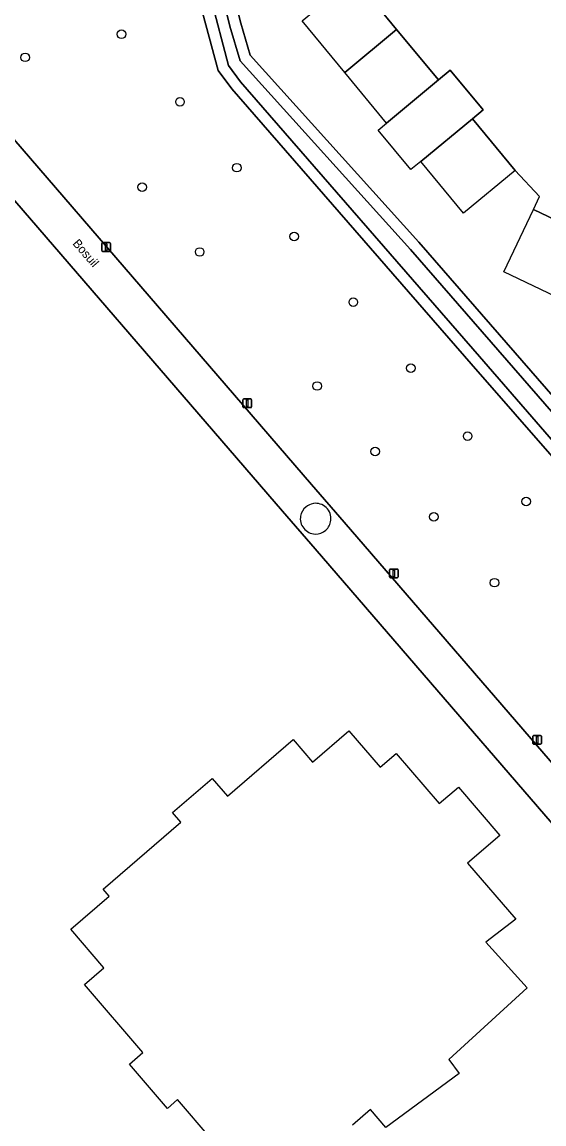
# Model space of a CAD drawing. Extents: x 156661 to 157576, y 383570 to 384425.
# Drawn here: x 156830 to 156889.4, y 383755 to 383880.2 of the extents above; entities that cross this region are included whole.
import ezdxf

# ---------------------------------------------------------------- set-up
doc = ezdxf.new("R2010")
doc.units = 0
for name, color, linetype in [('IMGEO_Boom', 7, 'Continuous'), ('IMGEO_Groenvoorziening', 7, 'Continuous'), ('IMGEO_Lichtmast', 7, 'Continuous'), ('IMGEO_Oever', 7, 'Continuous'), ('IMGEO_Openbare_ruimte_label', 7, 'Continuous'), ('IMGEO_Pand_vergunning_verleend', 7, 'Continuous'), ('IMGEO_Rijbaan_lokaal_gesloten', 7, 'Continuous'), ('IMGEO_Rijbaan_lokaal_open', 7, 'Continuous'), ('IMGEO_Waterloop', 7, 'Continuous')]:
    doc.layers.add(name, color=color, linetype=linetype)

msp = doc.modelspace()

# ---------------------------------------------------------------- linework, layer by layer
at = {"layer": 'IMGEO_Boom'}
for centre in [(156841.29, 383878.84), (156830.33, 383876.22), (156847.96, 383871.17), (156854.42, 383863.68), (156843.66, 383861.47), (156860.94, 383855.86), (156850.2, 383854.1), (156867.68, 383848.4), (156874.22, 383840.9), (156863.58, 383838.87), (156880.69, 383833.18), (156870.17, 383831.43), (156887.36, 383825.74), (156876.85, 383823.99), (156883.74, 383816.52)]:
    msp.add_circle(centre, 0.489, dxfattribs=at)
at = {"layer": 'IMGEO_Groenvoorziening'}
for points in [[(156851.52, 383893.46), (156854.87, 383880.1), (156855.95, 383876.48), (156875.13, 383855.23), (156891.46, 383836.51), (156911.62, 383812.79), (156912.8, 383811.32), (156913.72, 383811.62), (156932.37, 383827.97), (156950.38, 383842.94), (156962.3, 383852.37), (156962.64, 383852.87), (156967.11, 383858.58), (156983.42, 383879.38)], [(156930.61, 383784.8), (156881.09, 383841.39), (156853.84, 383872.65), (156852.3, 383874.71), (156848.11, 383890.33), (156847.87, 383891.87)], [(156820.25, 383877.09), (156862.92, 383827.69), (156866.64, 383823.38), (156904.91, 383779.13), (156906.37, 383777.46), (156907.59, 383778.51), (156909.46, 383776.35)], [(156863.33, 383820.38), (156859.63, 383824.66), (156822.23, 383867.92), (156821.46, 383867.3), (156814.7, 383875.12)], [(156903.48, 383771.4), (156901.63, 383773.6), (156902.83, 383774.64), (156901.78, 383775.88), (156863.33, 383820.38)]]:
    msp.add_lwpolyline(points, dxfattribs=at)
at = {"layer": 'IMGEO_Lichtmast'}
for p, q in [((156839.05, 383854.26), (156839.05, 383855.06)), ((156839.05, 383855.06), (156839.05, 383854.26)), ((156839.15, 383855.16), (156839.94, 383855.16)), ((156839.94, 383855.16), (156839.15, 383855.16)), ((156840.04, 383855.06), (156840.04, 383854.26)), ((156840.04, 383854.26), (156840.04, 383855.06)), ((156839.94, 383854.16), (156839.15, 383854.16)), ((156839.15, 383854.16), (156839.94, 383854.16)), ((156855.12, 383836.51), (156855.12, 383837.31)), ((156855.12, 383837.31), (156855.12, 383836.51)), ((156855.22, 383837.41), (156856.01, 383837.41)), ((156856.01, 383837.41), (156855.22, 383837.41)), ((156856.11, 383837.31), (156856.11, 383836.51)), ((156856.11, 383836.51), (156856.11, 383837.31)), ((156856.01, 383836.41), (156855.22, 383836.41)), ((156855.22, 383836.41), (156856.01, 383836.41)), ((156871.8, 383817.17), (156871.8, 383817.97)), ((156871.8, 383817.97), (156871.8, 383817.17)), ((156871.9, 383818.07), (156872.69, 383818.07)), ((156872.69, 383818.07), (156871.9, 383818.07)), ((156872.69, 383817.07), (156871.9, 383817.07)), ((156871.9, 383817.07), (156872.69, 383817.07)), ((156872.79, 383817.97), (156872.79, 383817.17)), ((156872.79, 383817.17), (156872.79, 383817.97)), ((156888.1, 383798.26), (156888.1, 383799.06)), ((156888.1, 383799.06), (156888.1, 383798.26)), ((156888.2, 383799.16), (156888.99, 383799.16)), ((156888.99, 383799.16), (156888.2, 383799.16)), ((156888.99, 383798.16), (156888.2, 383798.16)), ((156888.2, 383798.16), (156888.99, 383798.16)), ((156889.09, 383799.06), (156889.09, 383798.26)), ((156889.09, 383798.26), (156889.09, 383799.06))]:
    msp.add_line(p, q, dxfattribs=at)
for points in [[(156839.47, 383855.03), (156839.62, 383855.03), (156839.62, 383854.28), (156839.47, 383854.28), (156839.47, 383855.03)], [(156855.54, 383837.29), (156855.69, 383837.29), (156855.69, 383836.54), (156855.54, 383836.54), (156855.54, 383837.29)], [(156872.22, 383817.94), (156872.37, 383817.94), (156872.37, 383817.19), (156872.22, 383817.19), (156872.22, 383817.94)], [(156888.52, 383799.04), (156888.67, 383799.04), (156888.67, 383798.29), (156888.52, 383798.29), (156888.52, 383799.04)]]:
    msp.add_lwpolyline(points, dxfattribs=at)
for centre, start, end in [((156839.15, 383855.06), 90, 180), ((156839.15, 383855.06), 90, 180), ((156839.94, 383855.06), 0, 90), ((156839.94, 383855.06), 360, 90), ((156839.15, 383854.26), 180, 270), ((156839.15, 383854.26), 180, 270), ((156839.94, 383854.26), 270, 0), ((156839.94, 383854.26), 270, 0), ((156855.22, 383837.31), 90, 180), ((156855.22, 383837.31), 90, 180), ((156856.01, 383837.31), 0, 90), ((156856.01, 383837.31), 360, 90), ((156855.22, 383836.51), 180, 270), ((156855.22, 383836.51), 180, 270), ((156856.01, 383836.51), 270, 0), ((156856.01, 383836.51), 270, 0), ((156871.9, 383817.97), 90, 180), ((156871.9, 383817.97), 90, 180), ((156871.9, 383817.17), 180, 270), ((156871.9, 383817.17), 180, 270), ((156872.69, 383817.97), 0, 90), ((156872.69, 383817.97), 360, 90), ((156872.69, 383817.17), 270, 0), ((156872.69, 383817.17), 270, 0), ((156888.2, 383799.06), 90, 180), ((156888.2, 383799.06), 90, 180), ((156888.2, 383798.26), 180, 270), ((156888.2, 383798.26), 180, 270), ((156888.99, 383799.06), 0, 90), ((156888.99, 383799.06), 360, 90), ((156888.99, 383798.26), 270, 0), ((156888.99, 383798.26), 270, 0)]:
    msp.add_arc(centre, 0.1, start, end, dxfattribs=at)
at = {"layer": 'IMGEO_Oever'}
for points in [[(156983.42, 383879.38), (156967.11, 383858.58), (156962.64, 383852.87), (156962.3, 383852.37), (156950.38, 383842.94), (156932.37, 383827.97), (156913.72, 383811.62), (156912.8, 383811.32), (156911.62, 383812.79), (156891.46, 383836.51), (156875.13, 383855.23), (156855.95, 383876.48), (156854.87, 383880.1), (156851.52, 383893.46)], [(156931.62, 383785.15), (156882.05, 383842.23), (156854.83, 383873.45), (156853.47, 383875.28), (156849.46, 383890.63), (156849.07, 383892.88)], [(156850.28, 383893.2), (156853.64, 383879.76), (156854.82, 383875.84), (156874.18, 383854.39), (156890.49, 383835.68), (156910.64, 383811.98), (156912.36, 383809.83), (156914.36, 383810.5), (156933.19, 383827), (156951.18, 383841.95), (156963.24, 383851.49), (156963.69, 383852.15)], [(156847.87, 383891.87), (156848.11, 383890.33), (156852.3, 383874.71), (156853.84, 383872.65), (156881.09, 383841.39), (156930.61, 383784.8)]]:
    msp.add_lwpolyline(points, dxfattribs=at)
at = {"layer": 'IMGEO_Pand_vergunning_verleend'}
for points in [[(156889.67, 383885.38), (156894.72, 383879.41), (156896.06, 383880.54), (156900.83, 383874.91), (156899.53, 383873.82), (156903.35, 383869.31), (156905.81, 383866.4), (156902.9, 383863.94), (156900.02, 383858.15), (156903.71, 383856.52), (156901.77, 383852.45), (156894.87, 383855.73), (156888.17, 383858.92), (156888.87, 383860.39), (156886.09, 383863.36), (156881.23, 383869.25), (156882.45, 383870.26), (156878.72, 383874.77), (156877.36, 383873.65), (156872.6, 383879.4), (156864.96, 383888.65)], [(156851.51, 383753.3), (156847.67, 383757.77), (156846.52, 383756.78), (156842.21, 383761.79), (156843.75, 383763.11), (156837.08, 383770.87), (156839.28, 383772.76), (156835.53, 383777.13), (156839.89, 383780.88), (156839.2, 383781.69), (156848.05, 383789.31), (156847.11, 383790.4), (156851.63, 383794.28), (156853.36, 383792.27), (156860.83, 383798.69), (156863.05, 383796.11), (156867.18, 383799.67), (156870.73, 383795.54), (156872.56, 383797.11), (156877.46, 383791.41), (156879.64, 383793.29), (156884.35, 383787.8), (156880.69, 383784.66), (156886.17, 383778.28), (156882.75, 383775.65), (156887.48, 383770.46), (156878.55, 383762.33), (156879.73, 383760.73), (156871.37, 383754.59), (156869.62, 383756.64), (156867.58, 383754.88)]]:
    msp.add_lwpolyline(points, dxfattribs=at)
for points in [[(156872.6, 383879.4), (156866.72, 383874.49), (156861.85, 383880.38), (156867.76, 383885.26)], [(156871.47, 383868.75), (156866.72, 383874.49), (156872.6, 383879.4), (156877.36, 383873.65)], [(156881.23, 383869.25), (156875.35, 383864.39), (156874.24, 383863.47), (156870.52, 383867.96), (156871.47, 383868.75), (156877.36, 383873.65), (156878.72, 383874.77), (156882.45, 383870.26)], [(156875.35, 383864.39), (156881.23, 383869.25), (156886.09, 383863.36), (156880.21, 383858.5)], [(156894.87, 383855.73), (156891.56, 383848.63), (156884.8, 383851.85), (156888.17, 383858.92)]]:
    msp.add_lwpolyline(points, close=True, dxfattribs=at)
at = {"layer": 'IMGEO_Rijbaan_lokaal_gesloten'}
for centre, radius, start, end in [((156863.39, 383823.78), 1.74, 130.0856, 169.5908), ((156863.4, 383823.8), 1.73, 98.7141, 130.6426), ((156863.4, 383823.8), 1.74, 353.8037, 98.8143), ((156863.39, 383823.79), 1.74, 169.6525, 268.2313), ((156863.39, 383823.8), 1.75, 311.4273, 353.6497), ((156863.39, 383823.79), 1.74, 268.2893, 311.8666)]:
    msp.add_arc(centre, radius, start, end, dxfattribs=at)
at = {"layer": 'IMGEO_Rijbaan_lokaal_open'}
for points in [[(156908.89, 383774.52), (156906.37, 383777.46), (156904.91, 383779.13), (156866.64, 383823.38), (156862.92, 383827.69), (156820.25, 383877.09)], [(156815.17, 383876.09), (156822.23, 383867.92), (156859.63, 383824.66), (156863.33, 383820.38), (156901.78, 383775.88), (156902.83, 383774.64), (156904.73, 383772.43)]]:
    msp.add_lwpolyline(points, dxfattribs=at)
for centre, radius, start, end in [((156863.39, 383823.78), 1.74, 130.0856, 169.5908), ((156863.4, 383823.8), 1.73, 98.7141, 130.6426), ((156863.4, 383823.8), 1.74, 353.8037, 98.8143), ((156863.39, 383823.79), 1.74, 169.6525, 268.2313), ((156863.39, 383823.8), 1.75, 311.4273, 353.6497), ((156863.39, 383823.79), 1.74, 268.2893, 311.8666)]:
    msp.add_arc(centre, radius, start, end, dxfattribs=at)
at = {"layer": 'IMGEO_Waterloop'}
for points in [[(156849.07, 383892.88), (156849.46, 383890.63), (156853.47, 383875.28), (156854.83, 383873.45), (156882.05, 383842.23), (156931.62, 383785.15)], [(156984.64, 383878.72), (156967.57, 383857.07), (156963.69, 383852.15), (156963.24, 383851.49), (156951.18, 383841.95), (156933.19, 383827), (156914.36, 383810.5), (156912.36, 383809.83), (156910.64, 383811.98), (156890.49, 383835.68), (156874.18, 383854.39), (156854.82, 383875.84), (156853.64, 383879.76), (156850.28, 383893.2)]]:
    msp.add_lwpolyline(points, dxfattribs=at)

# ---------------------------------------------------------------- texts
at = {"layer": 'IMGEO_Openbare_ruimte_label'}
msp.add_text('Bosuil', height=1, rotation=310.8624, dxfattribs=at).set_placement((156835.68, 383855.03))

doc.saveas('drawing.dxf')
